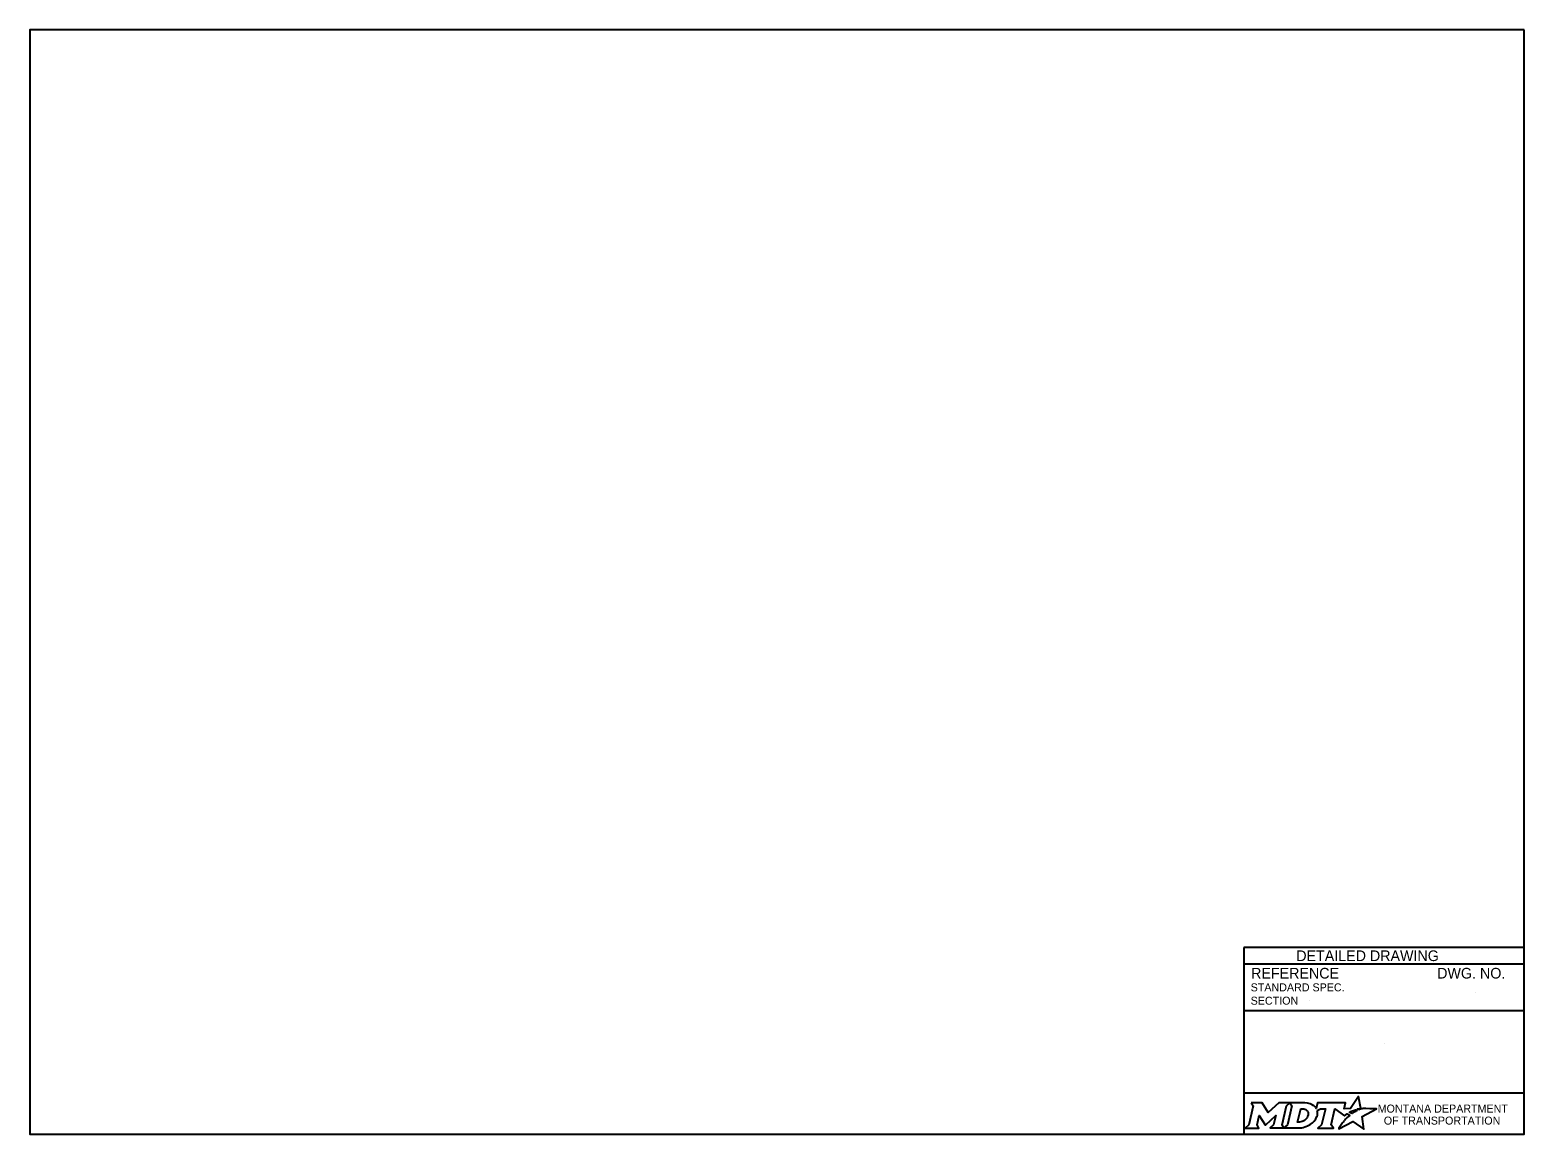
# Model space of a CAD drawing. Extents: x 49991.4 to 50048.3, y 49987.6 to 50018.3.
# Drawn here: x 50009.74 to 50020.94, y 49999.89 to 50008.16 of the extents above; entities that cross this region are included whole.
import ezdxf

# ---------------------------------------------------------------- set-up
doc = ezdxf.new("R2010")
doc.units = 0
for name, color, linetype in [('Default', 7, 'Continuous'), ('Level 1', 7, 'Continuous'), ('Level 4', 7, 'Continuous')]:
    doc.layers.add(name, color=color, linetype=linetype)

msp = doc.modelspace()

# ---------------------------------------------------------------- linework, layer by layer
at = {"layer": 'Default'}
for points in [[(50019.7, 50000.068), (50019.69, 50000.074), (50019.702, 50000.076), (50019.713, 50000.078), (50019.696, 50000.168), (50019.636, 50000.077), (50019.589, 50000.076), (50019.599, 50000.12), (50019.39, 50000.121), (50019.38, 50000.078), (50019.374, 50000.086)], [(50018.893, 50000.121), (50018.907, 50000.097), (50018.874, 49999.954), (50018.848, 49999.931), (50018.95, 49999.931), (50018.936, 49999.954), (50018.952, 50000.024), (50018.996, 49999.955), (50019.002, 49999.955), (50019.077, 50000.025), (50019.06, 49999.954), (50019.035, 49999.932), (50019.137, 49999.932), (50019.123, 49999.955), (50019.156, 50000.097)], [(50019.156, 50000.097), (50019.182, 50000.121), (50019.099, 50000.121), (50019.02, 50000.048), (50018.975, 50000.12), (50018.893, 50000.121)], [(50019.295, 50000.121), (50019.182, 50000.121), (50019.196, 50000.098), (50019.163, 49999.954), (50019.137, 49999.932), (50019.248, 49999.932)], [(50019.319, 50000.034), (50019.318, 50000.026), (50019.315, 50000.017), (50019.311, 50000.008), (50019.305, 50000.001), (50019.299, 49999.994), (50019.291, 49999.988), (50019.282, 49999.983), (50019.273, 49999.979), (50019.264, 49999.977), (50019.255, 49999.976), (50019.239, 49999.976), (50019.263, 50000.076), (50019.279, 50000.076), (50019.286, 50000.075), (50019.294, 50000.073), (50019.301, 50000.07), (50019.307, 50000.066), (50019.311, 50000.061), (50019.315, 50000.055), (50019.318, 50000.049), (50019.319, 50000.042), (50019.32, 50000.038), (50019.319, 50000.034)], [(50019.387, 50000.062), (50019.411, 50000.075), (50019.448, 50000.075), (50019.42, 49999.954), (50019.392, 49999.931), (50019.508, 49999.931), (50019.491, 49999.954), (50019.52, 50000.075), (50019.591, 50000.023), (50019.612, 50000.038), (50019.632, 50000.027)], [(50019.576, 49999.971), (50019.561, 49999.947), (50019.556, 49999.939), (50019.55, 49999.931), (50019.548, 49999.926), (50019.653, 49999.979), (50019.737, 49999.924), (50019.724, 50000.017), (50019.831, 50000.075), (50019.782, 50000.076), (50019.751, 50000.077), (50019.731, 50000.077), (50019.724, 50000.075), (50019.719, 50000.074), (50019.711, 50000.072), (50019.7, 50000.068)], [(50019.65, 50000.04), (50019.648, 50000.039), (50019.629, 50000.048), (50019.639, 50000.054), (50019.644, 50000.056), (50019.652, 50000.06), (50019.658, 50000.063), (50019.666, 50000.066), (50019.673, 50000.068), (50019.685, 50000.061), (50019.681, 50000.059), (50019.676, 50000.056), (50019.672, 50000.054), (50019.667, 50000.051), (50019.665, 50000.05), (50019.662, 50000.049), (50019.66, 50000.047), (50019.658, 50000.046), (50019.655, 50000.044), (50019.652, 50000.042), (50019.65, 50000.04)], [(50019.293, 49999.939), (50019.302, 49999.942), (50019.315, 49999.947), (50019.335, 49999.958)], [(50019.59, 49999.987), (50019.59, 49999.987)]]:
    msp.add_lwpolyline(points, dxfattribs=at)
for centre, radius, start, end in [((50019.319, 50000.042), 0.0709, 339.5329, 15.8582), ((50019.274, 50000.059), 0.118, 300.9103, 339.1383)]:
    msp.add_arc(centre, radius, start, end, dxfattribs=at)
for centre, major_axis, ratio, start_param, end_param in [((50019.293, 50000.073), (0.0834, -0.0037), 0.568097, 0.61298, 1.570796), ((50019.349, 50000.081), (0.0361, -0.0295), 0.469099, 1.225588, 1.570796), ((50019.248, 50000.08), (0, 0.148), 0.987302, 3.139398, 3.456847), ((50019.583, 49999.979), (-0.00694, -0.00806), 0.008222, 0, 3.137361), ((50019.6, 49999.997), (-0.0098, -0.0102), 0.016458, 3.141593, 6.279097), ((50019.621, 50000.017), (-0.0112, -0.0097), 0.021651, 3.157348, 6.283185)]:
    msp.add_ellipse(centre, major_axis=major_axis, ratio=ratio, start_param=start_param, end_param=end_param, dxfattribs=at)
at = {"layer": 'Level 1'}
msp.add_lwpolyline([(50020.938, 50008.165), (50009.737, 50008.165), (50009.737, 49999.886), (50020.938, 49999.886)], close=True, dxfattribs=at)
at = {"layer": 'Level 4'}
for p, q in [((50020.938, 50001.286), (50018.838, 50001.286)), ((50018.838, 50001.286), (50018.838, 49999.886)), ((50020.938, 50001.161), (50018.838, 50001.161)), ((50020.574, 50000.946), (50020.574, 50000.946)), ((50019.332, 50000.886), (50019.332, 50000.886)), ((50020.938, 50000.811), (50018.838, 50000.811)), ((50019.888, 50000.562), (50019.888, 50000.562)), ((50020.938, 50000.193), (50018.838, 50000.193))]:
    msp.add_line(p, q, dxfattribs=at)

# ---------------------------------------------------------------- texts
at = {"layer": 'Default'}
for s, p in [('MONTANA DEPARTMENT', (50019.84, 50000.047)), ('OF TRANSPORTATION', (50019.886, 49999.957))]:
    msp.add_text(s, height=0.06, rotation=360, dxfattribs=at).set_placement(p)
at = {"layer": 'Level 4'}
for s, height, p in [('DETAILED DRAWING', 0.0799, (50019.23, 50001.183)), ('REFERENCE', 0.08, (50018.891, 50001.052)), ('DWG. NO.', 0.08, (50020.286, 50001.052)), ('STANDARD SPEC.', 0.06, (50018.888, 50000.956)), ('SECTION', 0.06, (50018.888, 50000.856))]:
    msp.add_text(s, height=height, dxfattribs=at).set_placement(p)

doc.saveas('drawing.dxf')
